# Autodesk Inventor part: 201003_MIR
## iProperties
Created: 2007-12
Part Number: 201003_MIR
Material: Steel
Description: SIDE MOUNTING BAR
Document SubType Name: Modeling
Designer: jjohnson
Mass: 75.8289 g
Surface Area: 77.6706 cm^2
Volume: 9.65974 cm^3
Density: 7.85 g/cm^3
Component Category: Lower Component
Author: MM
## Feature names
1. TaggingFeature2
